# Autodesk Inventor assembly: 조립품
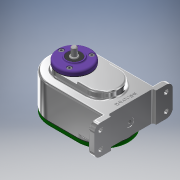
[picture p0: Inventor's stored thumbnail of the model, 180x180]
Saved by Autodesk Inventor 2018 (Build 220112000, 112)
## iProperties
Created: 2021-05
Part Number: 조립품
Material: 일반
Document SubType Name: Assembly
Designer: Admin
Author: Admin
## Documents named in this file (19)
- C:\Users\Admin\Desktop\710509V1009\조립품.iam
- C:\Users\Admin\Desktop\710509V1009\본체.ipt
- C:\Users\Admin\Desktop\710509V1009\베어링 6001.ipt
- 베어링 6001.ipt
- C:\Users\Admin\Desktop\710509V1009\베어링 6002.ipt
- 베어링 6002.ipt
- C:\Users\Admin\Desktop\710509V1009\볼트 M4.ipt
- C:\Users\Admin\Desktop\710509V1009\스퍼기어 A.ipt
- C:\Users\Admin\Desktop\710509V1009\스퍼기어 B.ipt
- C:\Users\Admin\Desktop\710509V1009\오일 실 12 22 7.ipt
- C:\Users\Admin\Desktop\710509V1009\축 A.ipt
- C:\Users\Admin\Desktop\710509V1009\축 B.ipt
- C:\Users\Admin\Desktop\710509V1009\칼라.ipt
- C:\Users\Admin\Desktop\710509V1009\커버 A.ipt
- C:\Users\Admin\Desktop\710509V1009\커버 B.ipt
- C:\Users\Admin\Desktop\710509V1009\키 4 x 4 x 12.ipt
- C:\Users\Admin\Desktop\710509V1009\키 5 x 5 x 12.ipt
- C:\Users\Admin\Desktop\710509V1009\개스킷 A.ipt
- C:\Users\Admin\Desktop\710509V1009\개스킷 B.ipt
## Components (2 placed, 2 different names)
1. 개스킷 A:1
2. 개스킷 B:1
